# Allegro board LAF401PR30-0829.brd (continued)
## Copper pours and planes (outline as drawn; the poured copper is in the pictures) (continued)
LG2_ISL9538 on IN1 (solid shape): 22.82,19.06 22.82,18.65 21.85,17.68 21.31,17.68 21.05,17.94 21.05,18.32 21.28,18.55 21.3,18.58 22.03,19.3 22.58,19.3
LX1_ISL9538 on TOP (solid shape): 19.14,26.3 19.14,25.66 18.88,25.41 15.76,25.41 15.58,25.6 15.58,26.38 15.74,26.55 18.89,26.55
LX1_ISL9538 on TOP (solid shape): 22.87,22.99 22.87,22.21 21.82,21.16 21.4,21.16 19.88,19.64 19.69,19.64 19.56,19.51 19.56,18.59 19.52,18.55 19.33,18.55 19.3,18.58 19.3,19.67 19.3,19.69 19.63,20.02 19.63,20.34 20.38,21.1 20.38,22.23 20.45,22.3 21.49,22.3 21.7,22.51 21.7,22.97 21.76,23.03 22.82,23.03
LX1_ISL9538 on BOTTOM (solid shape): 21,28.9 21,22.9 20.71,22.61 16.4,22.61 16.34,22.67 16.34,25.37 16.25,25.47 15.66,25.47 15.3,25.83 14.69,25.83 14.61,25.9 14.61,29.03 14.73,29.15 20.75,29.15
LX2_ISL9538 on TOP (solid shape): 29.6,24.53 29.93,24.53 30.07,24.39 30.07,22.99 29.96,22.88 27.95,22.88 27.95,24.47 28.01,24.53 29.6,24.53
LX2_ISL9538 on TOP (solid shape): 23.75,19.07 23.75,17.48 23.63,17.35 22.55,17.35 22.42,17.48 21.09,17.48 21.02,17.42 20.13,17.42 20.07,17.48 20.07,17.61 20.13,17.67 20.9,17.67 20.96,17.73 21.52,17.73 21.53,17.73 21.85,18.05 22.04,18.05 23.18,19.2 23.63,19.2
LX2_ISL9538 on BOTTOM (solid shape): 31.88,26.51 31.88,21.02 31.72,20.87 25.92,20.87 25.36,21.43 25.36,26.59 25.74,26.98 31.41,26.98
LX_1.8VALW on TOP (solid shape): 124.35,106.17 124.35,105.52 125.42,104.45 126.22,104.45 126.29,104.38 126.29,103.66 126.23,103.61 121.95,103.61 121.71,103.85 121.71,104.76 121.92,104.96 123.22,104.96 123.61,105.34 123.61,106.14 123.85,106.39 124.13,106.39
LX_1V_PRIM on TOP (solid shape): 131.2,110.94 131.2,109.9 130.36,109.05 130.36,107.89 129.37,106.9 127.09,106.9 127.02,106.91 126.95,106.91 126.67,107.18 126.67,107.99 126.87,108.19 127.72,108.19 127.72,108.2 128.07,108.55 128.07,109.44 128.21,109.58 129.89,109.58 130.44,110.13 130.44,110.91 130.54,111.01 131.14,111.01
LX_1VS_VCCIO on TOP (solid shape): 141.64,108.58 141.64,107.44 141.31,107.12 141.31,105.09 140.65,104.42 138.94,104.42 138.46,104.9 137.57,104.9 137.5,104.97 137.5,105.72 137.57,105.78 138.67,105.78 138.84,105.96 138.84,106.99 139.03,107.17 140.24,107.17 140.85,107.78 140.85,108.6 140.88,108.63 141.58,108.63
LX_3V on TOP (solid shape): 157.1,114.27 157.1,113.51 156.93,113.33 156.57,113.33 156.52,113.33 156.46,113.27 156.33,113.27 156.26,113.29 156.2,113.35 156.2,114.15 156.47,114.42 156.95,114.42
LX_3V on TOP (solid shape): 156.65,110.81 158.65,110.81 158.66,110.81 158.88,110.81 159.14,110.55 159.14,104.69 158.75,104.31 155.95,104.31 155.62,104.64 155.62,109.97 155.76,110.11 155.76,110.99 155.81,111.04 155.83,111.06 156.4,111.06
LX_3V on BOTTOM (solid shape): 157.99,109.77 157.99,107.99 158.37,107.61 159.16,107.61 159.36,107.41 159.36,104.51 159.07,104.22 155.83,104.22 155.43,104.63 155.43,109.78 155.62,109.97 157.79,109.97
LX_3V on IN1 (solid shape): 157.49,114.04 157.49,110.25 157.97,109.77 157.97,109.44 157.84,109.31 156.9,109.31 156.6,109.62 156.6,114.37 156.62,114.39 157.13,114.39
LX_5V on BOTTOM (solid shape): 166.93,116.83 166.93,115.79 166.86,115.72 166.73,115.72 166.65,115.79 166.65,115.84 166.5,115.99 166.04,115.99 165.87,116.17 165.87,116.68 166.22,117.04 166.73,117.04
LX_5V on BOTTOM (solid shape): 166.95,113.49 167.05,113.51 167.29,113.51 167.37,113.43 167.37,112.34 168.08,111.63 168.51,111.63 168.84,111.3 168.84,109.16 168.66,108.98 164.88,108.98 164.01,109.85 161.32,109.85 161.04,110.13 161.04,111.14 161.14,111.24 162.97,111.24 163.35,111.63 163.35,112.44 163.4,112.49 165.11,112.49 165.94,113.33 166.48,113.33 166.65,113.51 166.85,113.51
LX_5V on IN1 (solid shape): 166.93,116.83 166.93,115.87 166.58,115.51 166.58,113.1 167.14,112.54 167.14,111.78 166.91,111.55 165.87,111.55 165.46,111.96 165.46,116.05 166.01,116.6 166.01,116.83 166.22,117.04 166.73,117.04
LX_DDR on TOP (solid shape): 52.65,49.96 52.65,48.63 53.26,48.03 53.26,47.58 52.56,46.88 51.4,46.88 51.2,47.07 51.2,49.92 51.39,50.1 52.51,50.1
LX_DDR on BOTTOM (solid shape): 54.82,50.5 54.82,48.34 54,47.53 51.97,47.53 51.67,47.83 46.67,47.83 46.61,47.89 46.61,49.19 46.66,49.24 49.21,49.24 50.72,50.75 54.57,50.75
NB_PSID on BOTTOM (solid shape): 62.15,89.73 64.52,89.73 64.87,89.39 64.87,87.68 64.65,87.46 59.7,87.46 58.01,89.15 58.01,91.46 58.38,91.84 60.04,91.84
PBATT+_C on TOP (solid shape): 25.13,11.3 25.37,11.3 25.79,10.88 25.79,10.18 27.5,8.46 27.5,5.9 27.36,5.76 23.25,5.76 23.12,5.89 23.12,6.5 22.84,6.77 22.28,6.77 22.18,6.88 22.18,7.79 22.45,8.05 22.45,10.27 23.47,11.3 25.12,11.3
PBATT+_C on BOTTOM (solid shape): 26.67,13.31 26.67,8.25 26.46,8.04 22.78,8.04 22.48,8.34 22.48,10.66 22.52,10.73 22.59,10.76 22.97,11.12 22.59,11.47 22.52,11.5 22.48,11.57 22.48,13.29 22.77,13.57 26.4,13.57
POWER_SW_IN# on IN4 (solid shape): outline of 261 points within 296.85,71.8 298.86,74.9
RING2 on TOP (solid shape): 299.09,32.66 299.09,31.26 298.84,31.01 298.84,30.5 298.71,30.37 298.1,30.37 298,30.47 298,30.95 298.18,31.13 298.26,31.13 298.47,31.19 298.61,31.35 298.61,31.36 298.95,31.7 298.95,32.27 298.94,32.37 298.9,32.46 298.9,32.66 298.96,32.72 299.03,32.72
RING2 on BOTTOM (solid shape): 309.69,39.58 309.69,37.93 309.57,37.8 308.42,37.8 308.17,38.05 308.17,39.01 307.85,39.32 307.85,39.58 307.98,39.71 309.57,39.71
RING2 on IN1 (solid shape): 302.9,32.66 302.9,31.96 302.52,31.58 299.15,31.58 298.96,31.39 298.96,31.07 298.77,30.88 298.77,30.37 298.71,30.31 297.82,30.31 297.69,30.43 297.69,32.47 297.82,32.59 301.82,32.59 301.95,32.72 302.84,32.72
RING2 on IN1 (solid shape): 309.44,39.39 309.44,37.86 309,37.42 308.49,37.42 308.36,37.29 307.35,37.29 307.03,37.61 307.03,37.74 307.66,38.37 308.04,38.37 308.23,38.56 308.23,39 307.85,39.38 307.85,39.64 307.92,39.71 309.12,39.71
RING2_R on TOP (solid shape): 312.96,40.89 323.82,40.89 324.82,39.88 324.82,39.67 325.19,39.3 325.19,38.09 324.97,37.86 323.09,37.86 322.97,37.99 322.97,38.95 322.33,39.58 320.17,39.58 319.98,39.77 317.95,39.77 317.76,39.58 311.22,39.58 311.03,39.77 311.03,41.36 311.47,41.8 312.04,41.8
RING2_R on BOTTOM (solid shape): 312.36,41.67 312.36,40.09 312.11,39.83 311.09,39.83 310.96,39.71 310.96,38.94 310.88,38.85 309.97,38.85 309.95,38.88 309.95,39.68 309.95,39.68 309.95,40.53 310.08,40.66 311.03,40.66 311.22,40.85 311.22,41.55 311.47,41.8 312.23,41.8
SA_SW on BOTTOM (solid shape): 67.89,85.24 67.89,84.41 67.7,84.22 66.87,84.22 66.74,84.09 66.74,83.9 65.85,83.9 65.85,84.73 66.05,84.92 66.74,84.92 67.12,85.3 67.82,85.3
SA_SW on BOTTOM (solid shape): 78.11,86.76 77.16,86.76 77.16,85.87 78.11,85.87 78.11,84.92 75.25,84.92 74.81,85.36 72.2,85.36 72.2,86.38 75.13,86.38 75.44,86.7 75.44,87.46 75.7,87.71 78.11,87.71
SLEEVE on TOP (solid shape): 299.53,32.66 299.53,31.32 299.73,31.13 299.73,31.01 299.79,30.94 299.98,30.94 300.11,30.82 300.11,30.5 299.98,30.37 299.09,30.37 298.96,30.5 298.96,30.94 299.28,31.26 299.28,32.66 299.34,32.72 299.47,32.72
SLEEVE on BOTTOM (solid shape): 309.63,37.34 309.63,35.67 309.38,35.41 308.23,35.41 308.04,35.6 308.04,37.06 308.42,37.44 309.53,37.44
SLEEVE on IN1 (solid shape): 309.5,36.85 309.5,34.24 309.31,34.05 308.49,34.05 308.3,34.24 308.23,34.24 308.23,36.78 308.55,37.1 309.25,37.1
SLEEVE on IN1 (solid shape): 301.25,31.26 301.25,30.18 301.12,30.05 299.22,30.05 299.03,30.24 299.03,30.77 299.22,30.96 299.22,31.26 299.28,31.32 301.19,31.32
SLEEVE_R on TOP (solid shape): 313.06,39.13 313.06,38.56 312.18,37.67 311.28,37.67 311.09,37.86 311.09,39.01 311.41,39.32 312.87,39.32
SLEEVE_R on BOTTOM (solid shape): 314.2,39.64 314.2,39.01 312.81,37.61 312.81,36.47 312.62,36.28 311.98,36.28 311.85,36.15 311.4,36.15 310.95,36.25 310.65,35.9 310.65,35.9 310.01,35.9 309.95,35.96 309.95,36.53 310.01,36.59 310.6,36.59 311.31,37.3 311.31,37.94 311.28,37.97 311.28,39.26 311.47,39.45 312.11,39.45 312.36,39.71 314.14,39.71
SLEEVE_R on IN1 (solid shape): 322.46,40.53 322.46,40.52 322.57,40.4 322.57,38.23 322.27,37.93 320.49,37.93 320.26,38.16 320.26,39.45 320.07,39.64 318.52,39.64 318.01,39.13 314.65,39.13 314.27,38.75 311.47,38.75 311.28,38.94 311.28,40.09 311.73,40.53 312.55,40.53 312.87,40.85 322.14,40.85
SNB_+1VALWP on BOTTOM (solid shape): 175.14,91.97 175.14,89.55 175.07,89.49 174.06,89.49 174.06,92.03 174.12,92.09 175.01,92.09
SNUB_1.8VALW on TOP (solid shape): 126.37,106.75 126.37,105.13 126.29,105.05 125.37,105.05 125.29,105.12 125.29,105.79 125.73,106.22 125.73,106.77 125.78,106.82 126.3,106.82
SNUB_1V_PRIM on TOP (solid shape): 127.36,110.36 127.36,109.87 127.8,109.44 127.8,108.81 127.68,108.69 126.84,108.69 126.66,108.87 126.66,110.38 126.72,110.44 127.28,110.44
SNUB_1VS_VCCIO on TOP (solid shape): 137.73,108.02 137.73,107.29 137.9,107.12 138.54,107.12 138.65,107.01 138.65,106.39 138.58,106.32 137.15,106.32 137.03,106.45 137.03,108.01 137.12,108.1 137.65,108.1
SNUB_CHG1 on TOP (solid shape): 18.03,29.15 18.03,28.24 17.86,28.08 15.98,28.08 15.77,28.29 14.78,28.29 14.78,28.98 14.79,28.99 15.67,28.99 15.98,29.3 17.87,29.3
SNUB_CHG2 on TOP (solid shape): 32.9,23.77 32.9,22.88 30.61,22.88 30.61,24.53 32.14,24.53
SW_+1VALWP on BOTTOM (solid shape): 180.35,96.79 180.35,95.55 180.29,95.5 180.14,95.5 179.46,96.18 179.46,96.6 179.84,96.98 180.15,96.98
SW_+1VALWP on BOTTOM (solid shape): 180.79,93.17 180.79,91.78 181.36,91.2 182.31,91.2 182.31,88.98 182.25,88.92 177.04,88.92 176.73,89.24 176.73,91.14 176.92,91.14 176.92,91.15 177.31,91.15 177.55,91.38 177.55,91.77 177.55,91.78 177.55,92.41 178.76,92.41 179.33,92.98 179.84,92.98 180.12,93.26 180.7,93.26
SW_+1VALWP on IN4 (solid shape): 180.35,96.86 180.35,95.78 179.96,95.4 179.96,92.6 180.73,91.84 180.73,91.39 180.6,91.27 179.52,91.27 179.08,91.71 179.08,96.67 179.39,96.98 180.22,96.98
TBTA_CC2 on TOP (solid shape): 11.84,93.74 11.84,93.49 11.89,93.44 13.11,93.44 13.29,93.62 13.59,93.62 13.66,93.55 13.66,93.17 13.59,93.11 11.41,93.11 11.41,93.67 11.51,93.77 11.82,93.77
UG1_ISL9538 on TOP (solid shape): 19.63,20.85 19.63,20.59 19.5,20.47 19.5,20.07 19.17,19.74 19.17,19.73 19.15,19.7 19.15,18.61 19.1,18.56 18.97,18.56 18.93,18.61 18.93,20.66 19.25,20.97 19.5,20.97
UG1_ISL9538 on BOTTOM (solid shape): 9.73,25.21 9.73,24.03 9.55,23.85 8.61,23.85 8.43,24.03 8.43,25.06 8.6,25.23 9.72,25.23
UG1_ISL9538 on IN1 (solid shape): 9.62,24.38 9.78,24.38 9.94,24.22 9.94,23.64 9.82,23.53 8.97,23.53 8.43,24.07 8.43,24.84 8.58,24.99 9.01,24.99
UG1_ISL9538 on IN1 (solid shape): 19.63,20.53 19.5,20.4 19.5,20.02 19.37,19.89 18.93,19.89 18.86,19.96 18.86,21.99 19.63,21.99
UG2_ISL9538 on TOP (solid shape): 22.38,17.27 22.38,17.24 22.39,17.24 22.39,16.94 22.29,16.85 21.53,16.85 21.34,17.04 20.13,17.04 20.07,17.1 20.07,17.23 20.13,17.29 21.08,17.29 21.15,17.29 21.21,17.35 22.29,17.35
UG2_ISL9538 on BOTTOM (solid shape): 34.25,15.9 34.25,15.47 34.08,15.31 32.32,15.31 32.23,15.4 32.23,15.97 32.3,16.03 34.12,16.03
UG2_ISL9538 on IN1 (solid shape): 34.28,15.86 34.28,15.29 34.11,15.12 32.35,15.12 32.2,15.27 32.2,15.88 32.35,16.04 34.1,16.04
UG2_ISL9538 on IN1 (solid shape): 23.25,16.72 23.25,16.4 23.18,16.34 22.55,16.34 22.23,16.66 21.4,16.66 21.28,16.78 21.28,17.23 21.4,17.35 22.61,17.35
N16399089 on TOP (solid shape): 11.56,22.88 11.12,22.43 11.12,21.1 9.45,21.1 8.31,22.25 7.61,22.25 7.36,22.5 7.36,23.76 7.45,23.85 8.46,23.85 8.48,23.83 8.6,23.76 8.73,23.74 8.99,23.84 9.1,24.1 9.1,24.12 9.17,24.19 9.46,24.19 9.46,24.19 10.52,24.19 10.93,24.59 11.56,24.59
N16775433 on TOP (solid shape): 49.89,50.02 49.89,48.33 49.74,48.18 48.04,48.18 47.7,48.53 47.7,49.75 48.13,50.18 49.73,50.18
N16775513 on TOP (solid shape): 50.74,47.85 50.74,46.98 50.56,46.81 49.09,46.81 48.96,46.94 48.96,47.91 49.06,48.02 50.57,48.02
N16775517 on TOP (solid shape): 48.25,47.92 48.25,46.97 48.29,46.93 48.52,46.93 48.66,46.8 48.66,46.37 48.57,46.28 47.82,46.28 47.51,46.59 47.51,47.9 47.59,47.98 48.18,47.98
N16775517 on BOTTOM (solid shape): 48.92,47.27 48.92,46.48 48.7,46.26 48.06,46.26 47.86,46.46 47.86,47.31 47.96,47.41 48.77,47.41
N16783126 on TOP (solid shape): 153.32,110.86 154.18,110.86 154.4,111.08 155.05,111.08 155.15,110.98 155.15,107.69 154.95,107.49 153.85,107.49 153.7,107.64 153.7,109.37 153.36,109.71 152.47,109.71 152.28,109.9 152.28,109.9 152.28,111.4 152.35,111.47 152.71,111.47
N16784799 on BOTTOM (solid shape): 163.78,113.71 163.78,112.77 163.68,112.67 163.35,112.67 162.77,112.08 162.77,111.63 162.64,111.5 162.01,111.5 161.9,111.6 161.9,113.12 162.18,113.4 162.64,113.4 162.97,113.73 163.76,113.73
N17370862 on TOP (solid shape): 48.39,82.76 48.39,81.81 48.9,81.3 48.9,80.03 48.39,79.52 47.44,79.52 47.38,79.58 47.38,82.76 47.5,82.89 48.27,82.89
N17371029 on TOP (solid shape): 49.37,92.27 49.37,90.68 48.96,90.27 48.56,90.27 48.22,89.94 48.22,89.32 48.07,89.17 47.72,89.17 47.21,89.68 47.21,91.96 47.33,92.1 47.36,92.28 47.51,92.42 49.22,92.42
N18762349 on TOP (solid shape): 306.46,33.8 306.96,33.8 307.15,33.61 307.15,32.03 307.15,31.9 307.03,31.77 306.58,31.77 306.33,32.02 306.33,32.72 306.27,32.78 306.27,33.23 305.69,33.8 302.27,33.8 302.2,33.87 302.2,33.96 302.29,34.05 306.2,34.05
N18762426 on TOP (solid shape): 307.07,34.6 307.07,34.05 307.03,34 306.46,34 306.31,34.15 306.28,34.15 306.25,34.18 302.28,34.18 302.19,34.28 302.19,34.37 302.26,34.45 303.04,34.45 303.08,34.49 304.51,34.49 304.53,34.52 306.22,34.52 306.41,34.7 306.97,34.7
N32818355 on TOP (solid shape): 200.49,8.88 200.49,8.45 200.83,8.11 202.08,8.11 202.14,8.04 202.14,7.93 202.04,7.84 201.05,7.84 200.99,7.77 200.9,7.77 200.57,7.45 199.85,7.45 199.79,7.52 199.79,8.96 199.88,9.06 199.97,9.05 200.07,9.07 200.31,9.07
N35551558 on TOP (solid shape): 15.52,52.82 16.16,52.82 16.41,52.57 16.41,50.26 16.26,50.11 14.69,50.11 14.61,50.18 14.61,51.66 14.43,51.83 14.43,51.96 14.31,52.09 14.31,52.72 14.43,52.85 15.52,52.85
N35551576 on TOP (solid shape): 19.88,56.11 19.88,54.5 19.25,53.87 18.51,53.87 18.29,54.09 18.29,56.21 18.4,56.32 19.66,56.32
N35551584 on TOP (solid shape): 67.99,106.68 67.99,105.11 68.06,105.04 68.06,103.82 67.88,103.64 66.27,103.64 65.96,103.95 65.96,105.76 67.12,106.91 67.75,106.91
N35551584 on BOTTOM (solid shape): 71.11,105.33 71.11,104.13 70.89,103.91 70.04,103.91 69.64,104.31 69.64,104.34 69.61,104.34 69.44,104.51 69.44,104.88 70.01,105.44 71,105.44
N35551696 on TOP (solid shape): 4.77,51.01 9.99,51.01 10.14,50.86 10.55,50.86 10.67,50.73 10.67,50.18 10.55,50.06 4.13,50.06 3.88,49.8 3.88,49.1 3.37,49.1 3.37,50.25 3.12,50.5 3.12,51.58 3.43,51.9 3.88,51.9
N35551783 on TOP (solid shape): 10.55,44.29 10.55,43.45 10.93,43.07 10.93,40.53 10.67,40.28 10.04,40.28 9.28,39.52 7.5,39.52 7.12,39.9 7.12,40.53 7.75,41.17 9.66,41.17 9.78,41.29 9.78,42.94 9.74,42.98 9.74,44.3 9.83,44.39 10.44,44.39
N36626863 on BOTTOM (solid shape): 41.64,100.99 41.64,100.46 41.44,100.26 40.2,100.26 40.05,100.42 38.31,100.42 38.17,100.56 38.17,101.08 38.27,101.18 41.46,101.18
N36827741 on TOP (solid shape): 128.35,30.55 128.98,30.55 129.25,30.28 129.25,29.62 129.36,29.5 129.36,28.58 129.2,28.42 128.71,28.42 128.58,28.55 128.58,28.93 128.7,29.05 128.7,29.41 128.31,29.8 127.57,29.8 127.45,29.68 126.95,29.68 126.85,29.77 126.85,30.47 127.16,30.77 128.12,30.77
N39469996 on BOTTOM (solid shape): 67.88,88.28 67.89,88.28 68.39,87.78 68.39,86.76 68.33,86.7 68.2,86.7 68.14,86.76 68.14,87.46 67.76,87.84 66.93,87.84 66.74,87.65 65.85,87.65 65.85,88.28 66.78,88.28 66.85,88.35 67.81,88.35
N45988164 on BOTTOM (solid shape): 168.96,113.22 169.35,113.22 170.67,111.91 171.52,111.91 171.52,111.02 170.52,111.02 168.92,112.62 168.1,112.62 168.01,112.71 168.01,113.44 168.08,113.52 168.67,113.52
N47324022 on BOTTOM (solid shape): 182.12,93.21 182.12,93.11 184.09,91.14 184.6,91.14 184.6,90.25 183.77,90.25 181.93,92.09 181.62,92.09 181.42,92.28 181.42,93.2 181.49,93.26 182.07,93.26
N50204886 on TOP (solid shape): 21.34,23.7 21.34,23.07 21.21,22.94 19.12,22.94 19.06,23.01 19.06,23.7 19.12,23.77 21.28,23.77
N132000604 on TOP (solid shape): 24.58,16.27 23.94,16.27 23.94,16.81 23.96,16.91 23.94,17.01 23.94,18.37 24.58,18.37

Small or netless copper shapes (teardrops, artwork), in the pictures only: 91 on TOP, 34 on BOTTOM

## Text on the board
Ref Des/Silkscreen Bottom: H34 | H35 | M2X3 | H38 | ALL RIGHT RESERVED | REV:A02 | COPYRIGHT 2018 | PWB P/N:DHJHF
User.Comments: LA-F401P | 2019-08-29 | 2018-08-29 | DDM70 | Win
BODY_CENTER: L7 | L8 | L9 | L10 | IN2 | IN3 | VCC | IN4
User.39: trace wide | wide/space | SB_1_2mm-10L(4mil 50ohm)_WithOutC_151106.pdf | L2-GND1 | L3-IN1 | L4-GND2 | L1-TOP | L5-IN2 | L6-IN3 | L7-VCC | L8-IN4 | L9-GND3 | L10-BOT | LAYER | NAME | STACKUP: 10 LAYER | 39 ohm | 5.6 | 6.6 | 50 ohm | 4.8 | 3.5 | 4 | THICKNESS=1.2mm | 83 ohm | 3.9/3.5 | 3.6/3.5 | 3.5/3.6 | 4.8/4.3 | 3.7/3.6 | 85 ohm | 3.7/4.7 | 3.5/4.9 | 90 ohm | 100 ohm | 3.5/8.3 | 3/6.5
User.40: FIGURE | SIZE | 8.0 | 10.0 | 20.0 | 28.0 | 35.0 | 39.0 | 87.0 | 91.0 | 98.0 | 118.0 | 126.0 | 130.0 | 150.0 | 157.0 | 31.0 | 40.0 | 43.0 | 63.0 | 71.0 | 49.0x28.0 | 55.0x24.0 | 59.0x28.0 | 67.0x31.0 | 71.0x28.0 | 71.0x31.0 | 75.0x24.0 | 79.0x31.0 | 94.0x28.0 | 100.0x31.0 | 102.0x31.0 | 142.0x102.0 | DRILL CHART: TOP to BOTTOM | ALL UNITS ARE IN MILS | TOLERANCE | +3.0/-3.0 | +2.0/-2.0 | PLATED | NON-PLATED | QTY | 6225 | 1 | 19 | 42 | 10 | 5 | 3 | 6 | 2 | 8 | 7 | 4
